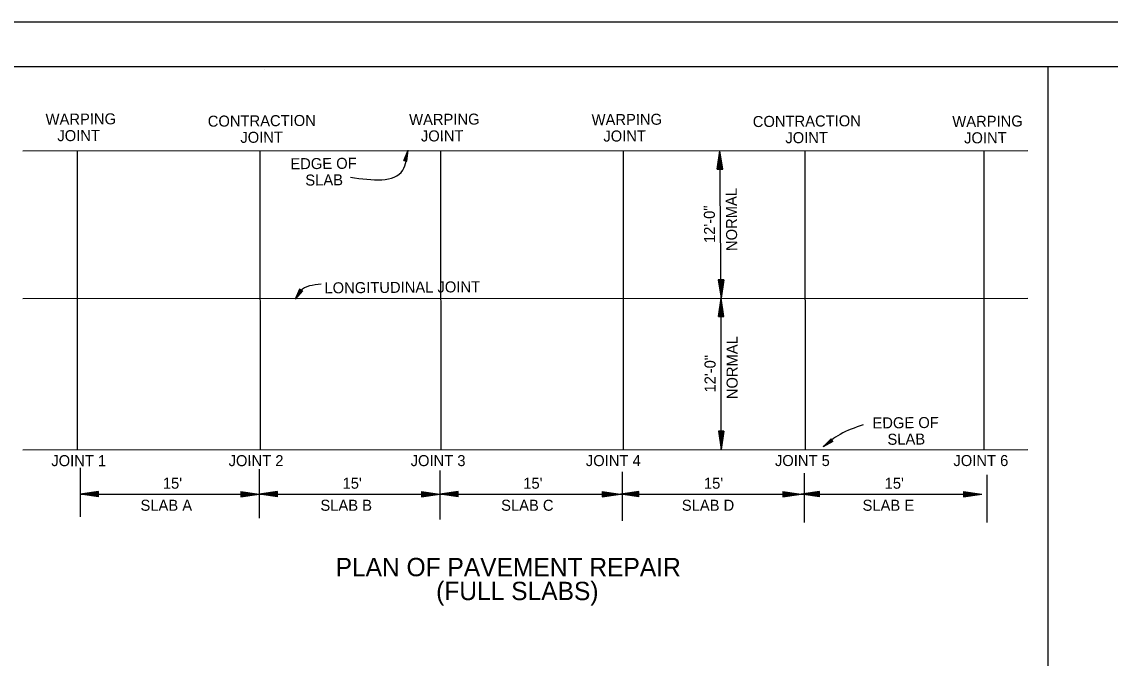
# Model space of a CAD drawing. Extents: x 1375738 to 1375905, y 380661 to 380875.
# Drawn here: x 1375810.09 to 1375857.49, y 380847.01 to 380874.73 of the extents above; entities that cross this region are included whole.
import ezdxf

# ---------------------------------------------------------------- set-up
doc = ezdxf.new("R2010")
doc.units = 0
for name, color, linetype in [('R_Border', 7, 'Continuous'), ('R_Draft', 7, 'Continuous'), ('R_No Plot', 7, 'Continuous')]:
    doc.layers.add(name, color=color, linetype=linetype)

msp = doc.modelspace()

# ---------------------------------------------------------------- linework, layer by layer
at = {"layer": 'R_Border'}
for p, q in [((1375744.419, 380872.783), (1375902.509, 380872.783)), ((1375820.679, 380872.653), (1375820.679, 380872.653)), ((1375820.679, 380872.653), (1375820.679, 380872.653)), ((1375854.78, 380770.053), (1375854.78, 380872.783))]:
    msp.add_line(p, q, dxfattribs=at)
at = {"layer": 'R_Draft'}
for p, q in [((1375829.519, 380872.783), (1375829.519, 380872.783)), ((1375810.143, 380869.112), (1375853.907, 380869.118)), ((1375812.52, 380856.095), (1375812.517, 380869.112)), ((1375820.482, 380856.096), (1375820.48, 380869.113)), ((1375826.727, 380868.695), (1375826.922, 380869.141)), ((1375826.739, 380868.692), (1375826.901, 380869.063)), ((1375826.751, 380868.689), (1375826.879, 380868.983)), ((1375826.763, 380868.687), (1375826.859, 380868.906)), ((1375826.831, 380868.668), (1375826.859, 380868.906)), ((1375826.843, 380868.665), (1375826.879, 380868.983)), ((1375826.855, 380868.661), (1375826.901, 380869.063)), ((1375826.866, 380868.658), (1375826.922, 380869.141)), ((1375828.35, 380856.097), (1375828.348, 380869.115)), ((1375836.295, 380856.099), (1375836.292, 380869.117)), ((1375840.381, 380868.315), (1375840.494, 380869.116)), ((1375840.401, 380868.315), (1375840.495, 380868.983)), ((1375840.421, 380868.316), (1375840.496, 380868.845)), ((1375840.544, 380862.689), (1375840.494, 380869.116)), ((1375840.621, 380868.317), (1375840.494, 380869.116)), ((1375840.601, 380868.317), (1375840.495, 380868.983)), ((1375840.58, 380868.317), (1375840.496, 380868.845)), ((1375844.215, 380856.1), (1375844.212, 380869.118)), ((1375852.002, 380856.101), (1375851.999, 380869.119)), ((1375826.727, 380868.695), (1375826.866, 380868.658)), ((1375826.775, 380868.683), (1375826.837, 380868.828)), ((1375826.786, 380868.68), (1375826.817, 380868.75)), ((1375826.808, 380868.674), (1375826.817, 380868.75)), ((1375826.819, 380868.671), (1375826.837, 380868.828)), ((1375840.441, 380868.316), (1375840.497, 380868.712)), ((1375840.462, 380868.316), (1375840.498, 380868.576)), ((1375840.482, 380868.316), (1375840.499, 380868.443)), ((1375840.56, 380868.317), (1375840.497, 380868.712)), ((1375840.54, 380868.317), (1375840.498, 380868.576)), ((1375840.519, 380868.317), (1375840.499, 380868.443)), ((1375840.381, 380868.315), (1375840.621, 380868.317)), ((1375840.658, 380863.489), (1375840.418, 380863.487)), ((1375840.418, 380863.487), (1375840.544, 380862.689)), ((1375840.438, 380863.488), (1375840.544, 380862.822)), ((1375840.458, 380863.488), (1375840.543, 380862.96)), ((1375840.478, 380863.488), (1375840.541, 380863.093)), ((1375840.499, 380863.488), (1375840.54, 380863.229)), ((1375840.519, 380863.488), (1375840.539, 380863.362)), ((1375840.557, 380863.489), (1375840.539, 380863.362)), ((1375840.577, 380863.489), (1375840.54, 380863.229)), ((1375840.597, 380863.489), (1375840.541, 380863.093)), ((1375840.617, 380863.489), (1375840.543, 380862.96)), ((1375840.658, 380863.489), (1375840.544, 380862.689)), ((1375840.638, 380863.489), (1375840.544, 380862.822)), ((1375810.143, 380862.684), (1375853.909, 380862.691)), ((1375822.19, 380863.091), (1375821.997, 380862.646)), ((1375822.312, 380863.015), (1375821.997, 380862.646)), ((1375822.2, 380863.085), (1375822.039, 380862.714)), ((1375822.302, 380863.021), (1375822.039, 380862.714)), ((1375822.211, 380863.079), (1375822.083, 380862.784)), ((1375822.292, 380863.028), (1375822.083, 380862.784)), ((1375822.221, 380863.072), (1375822.125, 380862.852)), ((1375822.282, 380863.034), (1375822.125, 380862.852)), ((1375822.231, 380863.066), (1375822.168, 380862.921)), ((1375822.271, 380863.041), (1375822.168, 380862.921)), ((1375822.312, 380863.015), (1375822.19, 380863.091)), ((1375822.241, 380863.06), (1375822.211, 380862.989)), ((1375822.261, 380863.047), (1375822.211, 380862.989)), ((1375840.425, 380861.889), (1375840.544, 380862.689)), ((1375840.546, 380856.099), (1375840.544, 380862.689)), ((1375840.665, 380861.888), (1375840.544, 380862.689)), ((1375840.445, 380861.889), (1375840.544, 380862.555)), ((1375840.465, 380861.889), (1375840.544, 380862.417)), ((1375840.485, 380861.888), (1375840.544, 380862.284)), ((1375840.645, 380861.888), (1375840.544, 380862.555)), ((1375840.625, 380861.889), (1375840.544, 380862.417)), ((1375840.605, 380861.889), (1375840.544, 380862.284)), ((1375840.425, 380861.889), (1375840.665, 380861.888)), ((1375840.506, 380861.888), (1375840.545, 380862.149)), ((1375840.526, 380861.888), (1375840.545, 380862.015)), ((1375840.584, 380861.889), (1375840.545, 380862.149)), ((1375840.564, 380861.889), (1375840.545, 380862.015)), ((1375840.425, 380856.899), (1375840.546, 380856.099)), ((1375840.665, 380856.899), (1375840.425, 380856.899)), ((1375840.445, 380856.899), (1375840.546, 380856.232)), ((1375840.465, 380856.899), (1375840.545, 380856.37)), ((1375840.485, 380856.899), (1375840.545, 380856.503)), ((1375840.506, 380856.899), (1375840.545, 380856.639)), ((1375840.526, 380856.899), (1375840.545, 380856.772)), ((1375840.584, 380856.899), (1375840.545, 380856.639)), ((1375840.625, 380856.899), (1375840.545, 380856.37)), ((1375840.605, 380856.899), (1375840.545, 380856.503)), ((1375840.564, 380856.899), (1375840.545, 380856.772)), ((1375840.665, 380856.899), (1375840.546, 380856.099)), ((1375840.645, 380856.899), (1375840.546, 380856.232)), ((1375845.333, 380856.561), (1375844.989, 380856.217)), ((1375845.34, 380856.551), (1375845.054, 380856.265)), ((1375845.347, 380856.541), (1375845.12, 380856.313)), ((1375845.354, 380856.531), (1375845.184, 380856.362)), ((1375845.361, 380856.521), (1375845.25, 380856.409)), ((1375845.418, 380856.444), (1375845.333, 380856.561)), ((1375810.144, 380856.094), (1375853.909, 380856.101)), ((1375845.418, 380856.444), (1375844.989, 380856.217)), ((1375845.411, 380856.454), (1375845.054, 380856.265)), ((1375845.403, 380856.464), (1375845.12, 380856.313)), ((1375845.396, 380856.473), (1375845.184, 380856.362)), ((1375845.389, 380856.483), (1375845.25, 380856.409)), ((1375845.368, 380856.511), (1375845.314, 380856.457)), ((1375845.381, 380856.493), (1375845.314, 380856.457)), ((1375812.641, 380855.308), (1375812.641, 380853.171)), ((1375820.426, 380855.248), (1375820.426, 380853.111)), ((1375828.294, 380855.187), (1375828.294, 380853.051)), ((1375836.238, 380855.126), (1375836.238, 380852.99)), ((1375844.157, 380855.065), (1375844.157, 380852.929)), ((1375852.117, 380855.003), (1375852.117, 380852.929)), ((1375813.441, 380854.273), (1375812.641, 380854.153)), ((1375812.641, 380854.153), (1375820.426, 380854.153)), ((1375813.441, 380854.033), (1375812.641, 380854.153)), ((1375813.441, 380854.253), (1375812.775, 380854.153)), ((1375813.441, 380854.053), (1375812.775, 380854.153)), ((1375813.441, 380854.232), (1375812.913, 380854.153)), ((1375813.441, 380854.073), (1375812.913, 380854.153)), ((1375813.441, 380854.212), (1375813.046, 380854.153)), ((1375813.441, 380854.093), (1375813.046, 380854.153)), ((1375813.441, 380854.192), (1375813.181, 380854.153)), ((1375813.441, 380854.114), (1375813.181, 380854.153)), ((1375813.441, 380854.171), (1375813.315, 380854.153)), ((1375813.441, 380854.134), (1375813.315, 380854.153)), ((1375813.441, 380854.033), (1375813.441, 380854.273)), ((1375819.626, 380854.273), (1375820.426, 380854.153)), ((1375819.626, 380854.273), (1375819.626, 380854.033)), ((1375819.626, 380854.253), (1375820.292, 380854.153)), ((1375819.626, 380854.232), (1375820.155, 380854.153)), ((1375819.626, 380854.212), (1375820.021, 380854.153)), ((1375819.626, 380854.191), (1375819.886, 380854.153)), ((1375819.626, 380854.171), (1375819.752, 380854.153)), ((1375819.626, 380854.033), (1375820.426, 380854.153)), ((1375819.626, 380854.113), (1375819.886, 380854.153)), ((1375819.626, 380854.073), (1375820.155, 380854.153)), ((1375819.626, 380854.053), (1375820.292, 380854.153)), ((1375819.626, 380854.093), (1375820.021, 380854.153)), ((1375819.626, 380854.134), (1375819.752, 380854.153)), ((1375821.226, 380854.273), (1375820.426, 380854.153)), ((1375820.426, 380854.153), (1375828.294, 380854.153)), ((1375821.226, 380854.033), (1375820.426, 380854.153)), ((1375821.226, 380854.253), (1375820.559, 380854.153)), ((1375821.226, 380854.053), (1375820.559, 380854.153)), ((1375821.226, 380854.232), (1375820.697, 380854.153)), ((1375821.226, 380854.073), (1375820.697, 380854.153)), ((1375821.226, 380854.212), (1375820.83, 380854.153)), ((1375821.226, 380854.093), (1375820.83, 380854.153)), ((1375821.226, 380854.192), (1375820.966, 380854.153)), ((1375821.226, 380854.114), (1375820.966, 380854.153)), ((1375821.226, 380854.171), (1375821.099, 380854.153)), ((1375821.226, 380854.134), (1375821.099, 380854.153)), ((1375821.226, 380854.033), (1375821.226, 380854.273)), ((1375827.494, 380854.273), (1375828.294, 380854.153)), ((1375827.494, 380854.273), (1375827.494, 380854.033)), ((1375827.494, 380854.253), (1375828.16, 380854.153)), ((1375827.494, 380854.232), (1375828.023, 380854.153)), ((1375827.494, 380854.212), (1375827.889, 380854.153)), ((1375827.494, 380854.191), (1375827.754, 380854.153)), ((1375827.494, 380854.171), (1375827.62, 380854.153)), ((1375827.494, 380854.033), (1375828.294, 380854.153)), ((1375827.494, 380854.113), (1375827.754, 380854.153)), ((1375827.494, 380854.073), (1375828.023, 380854.153)), ((1375827.494, 380854.053), (1375828.16, 380854.153)), ((1375827.494, 380854.093), (1375827.889, 380854.153)), ((1375827.494, 380854.134), (1375827.62, 380854.153)), ((1375829.094, 380854.273), (1375828.294, 380854.153)), ((1375828.294, 380854.153), (1375836.162, 380854.153)), ((1375829.094, 380854.033), (1375828.294, 380854.153)), ((1375829.094, 380854.253), (1375828.427, 380854.153)), ((1375829.094, 380854.053), (1375828.427, 380854.153)), ((1375829.094, 380854.232), (1375828.565, 380854.153)), ((1375829.094, 380854.073), (1375828.565, 380854.153)), ((1375829.094, 380854.212), (1375828.698, 380854.153)), ((1375829.094, 380854.093), (1375828.698, 380854.153)), ((1375829.094, 380854.192), (1375828.834, 380854.153)), ((1375829.094, 380854.114), (1375828.834, 380854.153)), ((1375829.094, 380854.171), (1375828.967, 380854.153)), ((1375829.094, 380854.134), (1375828.967, 380854.153)), ((1375829.094, 380854.033), (1375829.094, 380854.273)), ((1375835.362, 380854.273), (1375836.162, 380854.153)), ((1375835.362, 380854.273), (1375835.362, 380854.033)), ((1375835.362, 380854.253), (1375836.028, 380854.153)), ((1375835.362, 380854.232), (1375835.891, 380854.153)), ((1375835.362, 380854.212), (1375835.757, 380854.153)), ((1375835.362, 380854.191), (1375835.622, 380854.153)), ((1375835.362, 380854.171), (1375835.488, 380854.153)), ((1375835.362, 380854.033), (1375836.162, 380854.153)), ((1375835.362, 380854.113), (1375835.622, 380854.153)), ((1375835.362, 380854.073), (1375835.891, 380854.153)), ((1375835.362, 380854.053), (1375836.028, 380854.153)), ((1375835.362, 380854.093), (1375835.757, 380854.153)), ((1375835.362, 380854.134), (1375835.488, 380854.153)), ((1375836.962, 380854.273), (1375836.162, 380854.153)), ((1375836.162, 380854.153), (1375844.03, 380854.153)), ((1375836.962, 380854.033), (1375836.162, 380854.153)), ((1375836.962, 380854.253), (1375836.295, 380854.153)), ((1375836.962, 380854.053), (1375836.295, 380854.153)), ((1375836.962, 380854.232), (1375836.433, 380854.153)), ((1375836.962, 380854.073), (1375836.433, 380854.153)), ((1375836.962, 380854.212), (1375836.566, 380854.153)), ((1375836.962, 380854.093), (1375836.566, 380854.153)), ((1375836.962, 380854.192), (1375836.702, 380854.153)), ((1375836.962, 380854.114), (1375836.702, 380854.153)), ((1375836.962, 380854.171), (1375836.835, 380854.153)), ((1375836.962, 380854.134), (1375836.835, 380854.153)), ((1375836.962, 380854.033), (1375836.962, 380854.273)), ((1375843.23, 380854.273), (1375844.03, 380854.153)), ((1375843.23, 380854.273), (1375843.23, 380854.033)), ((1375843.23, 380854.253), (1375843.896, 380854.153)), ((1375843.23, 380854.232), (1375843.759, 380854.153)), ((1375843.23, 380854.212), (1375843.625, 380854.153)), ((1375843.23, 380854.191), (1375843.49, 380854.153)), ((1375843.23, 380854.171), (1375843.356, 380854.153)), ((1375843.23, 380854.033), (1375844.03, 380854.153)), ((1375843.23, 380854.113), (1375843.49, 380854.153)), ((1375843.23, 380854.073), (1375843.759, 380854.153)), ((1375843.23, 380854.053), (1375843.896, 380854.153)), ((1375843.23, 380854.093), (1375843.625, 380854.153)), ((1375843.23, 380854.134), (1375843.356, 380854.153)), ((1375844.83, 380854.273), (1375844.03, 380854.153)), ((1375844.03, 380854.153), (1375851.898, 380854.153)), ((1375844.83, 380854.033), (1375844.03, 380854.153)), ((1375844.83, 380854.253), (1375844.163, 380854.153)), ((1375844.83, 380854.053), (1375844.163, 380854.153)), ((1375844.83, 380854.232), (1375844.301, 380854.153)), ((1375844.83, 380854.073), (1375844.301, 380854.153)), ((1375844.83, 380854.212), (1375844.434, 380854.153)), ((1375844.83, 380854.093), (1375844.434, 380854.153)), ((1375844.83, 380854.192), (1375844.57, 380854.153)), ((1375844.83, 380854.114), (1375844.57, 380854.153)), ((1375844.83, 380854.171), (1375844.703, 380854.153)), ((1375844.83, 380854.134), (1375844.703, 380854.153)), ((1375844.83, 380854.033), (1375844.83, 380854.273)), ((1375851.098, 380854.273), (1375851.898, 380854.153)), ((1375851.098, 380854.273), (1375851.098, 380854.033)), ((1375851.098, 380854.253), (1375851.764, 380854.153)), ((1375851.098, 380854.232), (1375851.627, 380854.153)), ((1375851.098, 380854.212), (1375851.493, 380854.153)), ((1375851.098, 380854.191), (1375851.358, 380854.153)), ((1375851.098, 380854.171), (1375851.224, 380854.153)), ((1375851.098, 380854.033), (1375851.898, 380854.153)), ((1375851.098, 380854.113), (1375851.358, 380854.153)), ((1375851.098, 380854.073), (1375851.627, 380854.153)), ((1375851.098, 380854.053), (1375851.764, 380854.153)), ((1375851.098, 380854.093), (1375851.493, 380854.153)), ((1375851.098, 380854.134), (1375851.224, 380854.153))]:
    msp.add_line(p, q, dxfattribs=at)
for points in [[(1375824.405, 380867.955), (1375826.686, 380868.265), (1375826.922, 380869.141)], [(1375823.126, 380863.299), (1375822.229, 380863.018), (1375821.997, 380862.646)], [(1375846.729, 380857.171), (1375845.724, 380856.76), (1375844.989, 380856.217)]]:
    msp.add_spline(points, degree=3, dxfattribs=at)
at = {"layer": 'R_No Plot'}
msp.add_line((1375738.219, 380874.73), (1375904.885, 380874.73), dxfattribs=at)
for points in [[(1375738.215, 380874.73), (1375904.885, 380874.73), (1375904.885, 380768.061), (1375738.215, 380768.061)], [(1375861.379, 380872.783), (1375871.189, 380872.783), (1375871.189, 380867.843), (1375879.245, 380867.843), (1375890.845, 380867.843), (1375890.845, 380851.508), (1375902.449, 380851.508), (1375902.509, 380770.053), (1375744.419, 380770.053), (1375744.419, 380872.783)]]:
    msp.add_lwpolyline(points, close=True, dxfattribs=at)

# ---------------------------------------------------------------- texts
at = {"layer": 'R_Draft'}
for s, height, rotation, p in [('WARPING', 0.48, 0.45, (1375811.134, 380870.24)), ('WARPING', 0.48, 0.45, (1375826.964, 380870.228)), ('CONTRACTION', 0.47998, 0.45, (1375818.195, 380870.159)), ('WARPING', 0.48, 0.45, (1375834.909, 380870.222)), ('CONTRACTION', 0.47998, 0.45, (1375841.927, 380870.144)), ('WARPING', 0.48, 0.45, (1375850.616, 380870.144)), ('JOINT', 0.48, 0.45, (1375811.646, 380869.527)), ('JOINT', 0.48, 0.45, (1375819.614, 380869.454)), ('JOINT', 0.48, 0.45, (1375827.476, 380869.515)), ('JOINT', 0.48, 0.45, (1375835.421, 380869.51)), ('JOINT', 0.48, 0.45, (1375843.346, 380869.438)), ('JOINT', 0.48, 0.45, (1375851.128, 380869.432)), ('EDGE OF', 0.48, 0.45, (1375821.79, 380868.306)), ('SLAB', 0.48, 0.45, (1375822.442, 380867.595)), ('NORMAL', 0.48, 90.45, (1375841.248, 380864.747)), ('12\'-0"', 0.48, 90.45, (1375840.285, 380865.097)), ('LONGITUDINAL JOINT', 0.47998, 0.45, (1375823.276, 380862.899)), ('NORMAL', 0.48, 90.0083, (1375841.265, 380858.292)), ('12\'-0"', 0.48, 90.0083, (1375840.305, 380858.583)), ('EDGE OF', 0.48, 0.45, (1375847.138, 380857.017)), ('SLAB', 0.48, 0.45, (1375847.79, 380856.306)), ('JOINT 1', 0.48, 0.0085, (1375811.38, 380855.375)), ('JOINT 2', 0.48, 0.0085, (1375819.1, 380855.376)), ('JOINT 3', 0.48, 0.0085, (1375827.027, 380855.377)), ('JOINT 4', 0.48, 0.0085, (1375834.656, 380855.378)), ('JOINT 5', 0.48, 0.0085, (1375842.89, 380855.38)), ('JOINT 6', 0.48, 0.0085, (1375850.662, 380855.38))]:
    msp.add_text(s, height=height, rotation=rotation, dxfattribs=at).set_placement(p)
for s, height, p in [("15'", 0.48, (1375816.237, 380854.393)), ("15'", 0.48, (1375824.063, 380854.393)), ("15'", 0.48, (1375831.931, 380854.393)), ("15'", 0.48, (1375839.799, 380854.393)), ("15'", 0.48, (1375847.667, 380854.393)), ('SLAB A', 0.48, (1375815.264, 380853.433)), ('SLAB B', 0.48, (1375823.098, 380853.433)), ('SLAB C', 0.48, (1375830.967, 380853.433)), ('SLAB D', 0.48, (1375838.835, 380853.433)), ('SLAB E', 0.48, (1375846.704, 380853.433)), ('PLAN OF PAVEMENT REPAIR', 0.7996, (1375823.758, 380850.581)), ('(FULL SLABS)', 0.7996, (1375828.137, 380849.541))]:
    msp.add_text(s, height=height, dxfattribs=at).set_placement(p)

doc.saveas('drawing.dxf')
